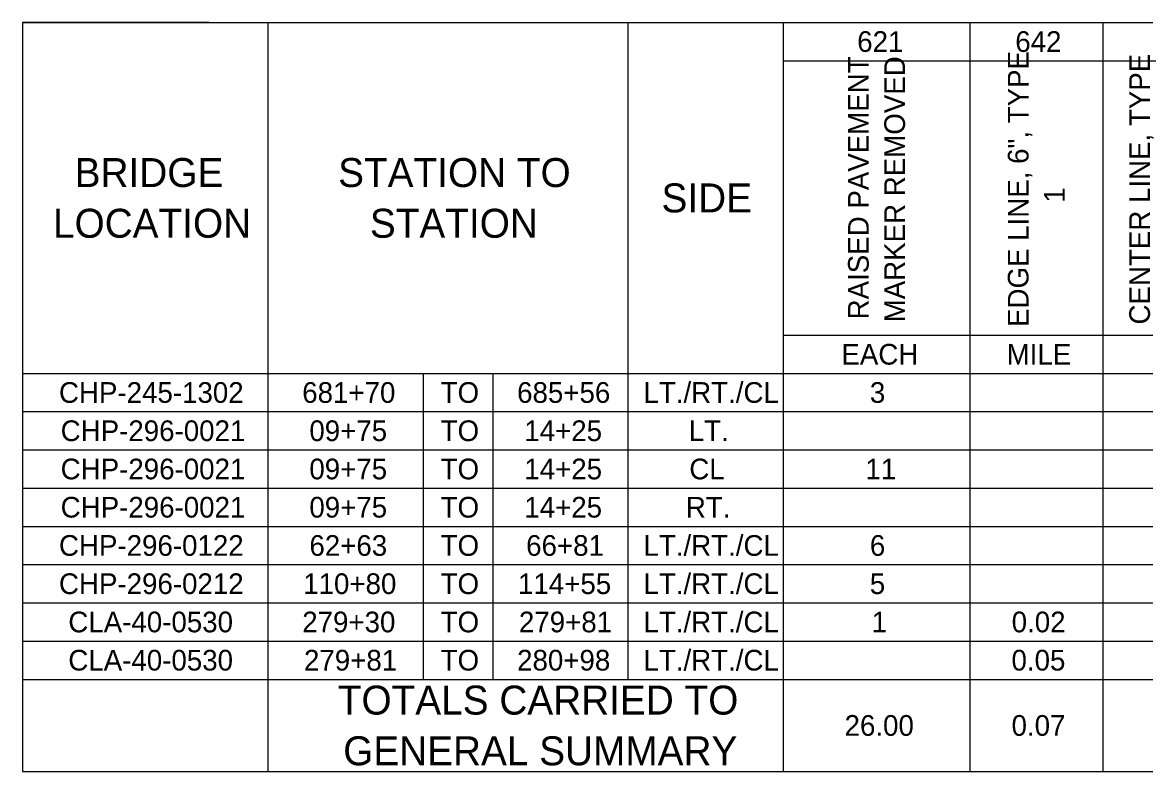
# Model space of a CAD drawing. Extents: x -49 to 78, y -12 to 34.
# Drawn here: x 9.03 to 17.24, y 28.25 to 33.74 of the extents above; entities that cross this region are included whole.
import ezdxf

# ---------------------------------------------------------------- set-up
doc = ezdxf.new("R2010")
doc.units = 0
doc.layers.add('SH_Text', color=7, linetype='Continuous')

msp = doc.modelspace()

# ---------------------------------------------------------------- linework, layer by layer
at = {"layer": 'SH_Text'}
for p, q in [((9.028, 33.7363), (23.7197, 33.7363)), ((9.028, 33.7363), (9.028, 28.2516)), ((10.8232, 33.7363), (10.8232, 28.2516)), ((13.4585, 33.7363), (13.4585, 28.9268)), ((14.595, 33.7363), (14.595, 28.2516)), ((15.9621, 33.7363), (15.9621, 28.2516)), ((16.9338, 33.7363), (16.9338, 28.2516)), ((14.595, 33.4563), (23.7197, 33.4563)), ((14.595, 31.4468), (23.7197, 31.4468)), ((9.028, 31.1668), (23.7197, 31.1668)), ((11.9597, 31.1668), (11.9597, 28.9268)), ((12.4703, 31.1668), (12.4703, 28.9268)), ((9.028, 30.8868), (23.7197, 30.8868)), ((9.028, 30.6068), (23.7197, 30.6068)), ((9.028, 30.3268), (23.7197, 30.3268)), ((9.028, 30.0468), (23.7197, 30.0468)), ((9.028, 29.7668), (23.7197, 29.7668)), ((9.028, 29.4868), (23.7197, 29.4868)), ((9.028, 29.2068), (23.7197, 29.2068)), ((9.028, 28.9268), (23.7197, 28.9268)), ((9.028, 28.2516), (23.7197, 28.2516))]:
    msp.add_line(p, q, dxfattribs=at)
for points in [[(9.028, 33.7363), (9.028, 33.7363), (9.028, 33.7363), (9.028, 33.7363)], [(9.028, 33.7363), (9.028, 33.7363), (9.028, 33.7363), (9.028, 33.7363)], [(9.028, 33.7363), (9.5385, 33.7363), (9.5385, 33.7363), (9.028, 33.7363)], [(9.028, 33.7363), (9.028, 33.7363), (9.028, 33.7363), (9.028, 33.7363)], [(9.028, 33.7363), (10.1644, 33.7363), (10.1644, 33.7363), (9.028, 33.7363)], [(9.028, 33.7363), (10.395, 33.7363), (10.395, 33.7363), (9.028, 33.7363)], [(9.028, 33.7363), (9.9997, 33.7363), (9.9997, 33.7363), (9.028, 33.7363)], [(9.028, 33.7363), (10.0985, 33.7363), (10.0985, 33.7363), (9.028, 33.7363)], [(9.028, 33.7363), (9.9668, 33.7363), (9.9668, 33.7363), (9.028, 33.7363)], [(9.028, 33.7363), (9.8185, 33.7363), (9.8185, 33.7363), (9.028, 33.7363)], [(9.028, 33.7363), (9.9174, 33.7363), (9.9174, 33.7363), (9.028, 33.7363)], [(9.028, 33.7363), (9.9338, 33.7363), (9.9338, 33.7363), (9.028, 33.7363)], [(9.028, 33.7363), (9.9174, 33.7363), (9.9174, 33.7363), (9.028, 33.7363)], [(9.028, 33.7363), (10.3291, 33.7363), (10.3291, 33.7363), (9.028, 33.7363)], [(9.028, 33.7363), (9.028, 33.7363), (9.028, 33.7363), (9.028, 33.7363)], [(9.028, 33.7363), (9.028, 33.7363), (9.028, 33.7363), (9.028, 33.7363)], [(9.028, 33.7363), (9.5385, 33.7363), (9.5385, 33.7363), (9.028, 33.7363)], [(9.028, 33.7363), (9.028, 33.7363), (9.028, 33.7363), (9.028, 33.7363)], [(9.028, 33.7363), (10.1644, 33.7363), (10.1644, 33.7363), (9.028, 33.7363)], [(9.028, 33.7363), (10.395, 33.7363), (10.395, 33.7363), (9.028, 33.7363)], [(9.028, 33.7363), (9.9997, 33.7363), (9.9997, 33.7363), (9.028, 33.7363)], [(9.028, 33.7363), (10.0985, 33.7363), (10.0985, 33.7363), (9.028, 33.7363)], [(9.028, 33.7363), (9.9668, 33.7363), (9.9668, 33.7363), (9.028, 33.7363)], [(9.028, 33.7363), (9.8185, 33.7363), (9.8185, 33.7363), (9.028, 33.7363)], [(9.028, 33.7363), (9.9174, 33.7363), (9.9174, 33.7363), (9.028, 33.7363)], [(9.028, 33.7363), (9.9338, 33.7363), (9.9338, 33.7363), (9.028, 33.7363)], [(9.028, 33.7363), (9.9174, 33.7363), (9.9174, 33.7363), (9.028, 33.7363)], [(9.028, 33.7363), (10.3291, 33.7363), (10.3291, 33.7363), (9.028, 33.7363)], [(9.028, 33.7363), (9.028, 33.7363), (9.028, 33.7363), (9.028, 33.7363)], [(9.028, 33.7363), (9.028, 33.7363), (9.028, 33.7363), (9.028, 33.7363)], [(9.028, 33.7363), (9.5385, 33.7363), (9.5385, 33.7363), (9.028, 33.7363)], [(9.028, 33.7363), (9.028, 33.7363), (9.028, 33.7363), (9.028, 33.7363)], [(9.028, 33.7363), (10.1644, 33.7363), (10.1644, 33.7363), (9.028, 33.7363)], [(9.028, 33.7363), (10.395, 33.7363), (10.395, 33.7363), (9.028, 33.7363)], [(9.028, 33.7363), (9.9997, 33.7363), (9.9997, 33.7363), (9.028, 33.7363)], [(9.028, 33.7363), (10.0985, 33.7363), (10.0985, 33.7363), (9.028, 33.7363)], [(9.028, 33.7363), (9.9668, 33.7363), (9.9668, 33.7363), (9.028, 33.7363)], [(9.028, 33.7363), (9.8185, 33.7363), (9.8185, 33.7363), (9.028, 33.7363)], [(9.028, 33.7363), (9.9174, 33.7363), (9.9174, 33.7363), (9.028, 33.7363)], [(9.028, 33.7363), (9.9338, 33.7363), (9.9338, 33.7363), (9.028, 33.7363)], [(9.028, 33.7363), (9.9174, 33.7363), (9.9174, 33.7363), (9.028, 33.7363)], [(9.028, 33.7363), (10.3291, 33.7363), (10.3291, 33.7363), (9.028, 33.7363)], [(9.028, 33.7363), (9.028, 33.7363), (9.028, 33.7363), (9.028, 33.7363)], [(9.028, 33.7363), (9.028, 33.7363), (9.028, 33.7363), (9.028, 33.7363)], [(9.028, 33.7363), (9.5385, 33.7363), (9.5385, 33.7363), (9.028, 33.7363)], [(9.028, 33.7363), (9.028, 33.7363), (9.028, 33.7363), (9.028, 33.7363)], [(9.028, 33.7363), (10.1644, 33.7363), (10.1644, 33.7363), (9.028, 33.7363)], [(9.028, 33.7363), (10.395, 33.7363), (10.395, 33.7363), (9.028, 33.7363)], [(9.028, 33.7363), (9.9997, 33.7363), (9.9997, 33.7363), (9.028, 33.7363)], [(9.028, 33.7363), (10.0985, 33.7363), (10.0985, 33.7363), (9.028, 33.7363)], [(9.028, 33.7363), (9.9668, 33.7363), (9.9668, 33.7363), (9.028, 33.7363)], [(9.028, 33.7363), (9.8185, 33.7363), (9.8185, 33.7363), (9.028, 33.7363)], [(9.028, 33.7363), (9.9174, 33.7363), (9.9174, 33.7363), (9.028, 33.7363)], [(9.028, 33.7363), (9.9338, 33.7363), (9.9338, 33.7363), (9.028, 33.7363)], [(9.028, 33.7363), (9.9174, 33.7363), (9.9174, 33.7363), (9.028, 33.7363)], [(9.028, 33.7363), (10.3291, 33.7363), (10.3291, 33.7363), (9.028, 33.7363)], [(9.028, 33.7363), (9.9997, 33.7363), (9.9997, 33.7363), (9.028, 33.7363)], [(9.028, 33.7363), (9.8515, 33.7363), (9.8515, 33.7363), (9.028, 33.7363)], [(9.028, 33.7363), (9.028, 33.7363), (9.028, 33.7363), (9.028, 33.7363)], [(9.028, 33.7363), (9.5385, 33.7363), (9.5385, 33.7363), (9.028, 33.7363)], [(9.028, 33.7363), (9.028, 33.7363), (9.028, 33.7363), (9.028, 33.7363)], [(9.028, 33.7363), (10.1644, 33.7363), (10.1644, 33.7363), (9.028, 33.7363)], [(9.028, 33.7363), (10.395, 33.7363), (10.395, 33.7363), (9.028, 33.7363)], [(9.028, 33.7363), (9.9997, 33.7363), (9.9997, 33.7363), (9.028, 33.7363)], [(9.028, 33.7363), (10.0985, 33.7363), (10.0985, 33.7363), (9.028, 33.7363)], [(9.028, 33.7363), (9.9668, 33.7363), (9.9668, 33.7363), (9.028, 33.7363)], [(9.028, 33.7363), (9.8185, 33.7363), (9.8185, 33.7363), (9.028, 33.7363)], [(9.028, 33.7363), (9.9174, 33.7363), (9.9174, 33.7363), (9.028, 33.7363)], [(9.028, 33.7363), (9.9338, 33.7363), (9.9338, 33.7363), (9.028, 33.7363)], [(9.028, 33.7363), (9.9174, 33.7363), (9.9174, 33.7363), (9.028, 33.7363)], [(9.028, 33.7363), (10.3291, 33.7363), (10.3291, 33.7363), (9.028, 33.7363)], [(9.028, 33.7363), (9.9997, 33.7363), (9.9997, 33.7363), (9.028, 33.7363)], [(9.028, 33.7363), (9.8515, 33.7363), (9.8515, 33.7363), (9.028, 33.7363)], [(9.028, 33.7363), (9.6868, 33.7363), (9.6868, 33.7363), (9.028, 33.7363)], [(9.028, 33.7363), (9.5056, 33.7363), (9.5056, 33.7363), (9.028, 33.7363)], [(9.028, 33.7363), (9.5385, 33.7363), (9.5385, 33.7363), (9.028, 33.7363)], [(9.028, 33.7363), (9.6374, 33.7363), (9.6374, 33.7363), (9.028, 33.7363)], [(9.028, 33.7363), (9.4068, 33.7363), (9.4068, 33.7363), (9.028, 33.7363)], [(9.028, 33.7363), (10.1644, 33.7363), (10.1644, 33.7363), (9.028, 33.7363)], [(9.028, 33.7363), (10.395, 33.7363), (10.395, 33.7363), (9.028, 33.7363)], [(9.028, 33.7363), (9.9997, 33.7363), (9.9997, 33.7363), (9.028, 33.7363)], [(9.028, 33.7363), (10.0985, 33.7363), (10.0985, 33.7363), (9.028, 33.7363)], [(9.028, 33.7363), (9.9668, 33.7363), (9.9668, 33.7363), (9.028, 33.7363)], [(9.028, 33.7363), (9.8185, 33.7363), (9.8185, 33.7363), (9.028, 33.7363)], [(9.028, 33.7363), (9.9174, 33.7363), (9.9174, 33.7363), (9.028, 33.7363)], [(9.028, 33.7363), (9.9338, 33.7363), (9.9338, 33.7363), (9.028, 33.7363)], [(9.028, 33.7363), (9.9174, 33.7363), (9.9174, 33.7363), (9.028, 33.7363)], [(9.028, 33.7363), (10.3291, 33.7363), (10.3291, 33.7363), (9.028, 33.7363)], [(9.028, 33.7363), (9.9997, 33.7363), (9.9997, 33.7363), (9.028, 33.7363)], [(9.028, 33.7363), (9.8515, 33.7363), (9.8515, 33.7363), (9.028, 33.7363)], [(9.028, 33.7363), (9.6868, 33.7363), (9.6868, 33.7363), (9.028, 33.7363)], [(9.028, 33.7363), (9.5056, 33.7363), (9.5056, 33.7363), (9.028, 33.7363)], [(9.028, 33.7363), (9.5385, 33.7363), (9.5385, 33.7363), (9.028, 33.7363)], [(9.028, 33.7363), (9.6374, 33.7363), (9.6374, 33.7363), (9.028, 33.7363)], [(9.028, 33.7363), (9.4068, 33.7363), (9.4068, 33.7363), (9.028, 33.7363)], [(9.028, 33.7363), (10.1644, 33.7363), (10.1644, 33.7363), (9.028, 33.7363)], [(9.028, 33.7363), (10.395, 33.7363), (10.395, 33.7363), (9.028, 33.7363)], [(9.028, 33.7363), (9.9997, 33.7363), (9.9997, 33.7363), (9.028, 33.7363)], [(9.028, 33.7363), (10.0985, 33.7363), (10.0985, 33.7363), (9.028, 33.7363)], [(9.028, 33.7363), (9.9668, 33.7363), (9.9668, 33.7363), (9.028, 33.7363)], [(9.028, 33.7363), (9.8185, 33.7363), (9.8185, 33.7363), (9.028, 33.7363)], [(9.028, 33.7363), (9.9174, 33.7363), (9.9174, 33.7363), (9.028, 33.7363)], [(9.028, 33.7363), (9.9338, 33.7363), (9.9338, 33.7363), (9.028, 33.7363)], [(9.028, 33.7363), (9.9174, 33.7363), (9.9174, 33.7363), (9.028, 33.7363)], [(9.028, 33.7363), (10.3291, 33.7363), (10.3291, 33.7363), (9.028, 33.7363)], [(9.028, 33.7363), (9.9997, 33.7363), (9.9997, 33.7363), (9.028, 33.7363)], [(9.028, 33.7363), (9.8515, 33.7363), (9.8515, 33.7363), (9.028, 33.7363)], [(9.028, 33.7363), (9.6868, 33.7363), (9.6868, 33.7363), (9.028, 33.7363)], [(9.028, 33.7363), (9.5056, 33.7363), (9.5056, 33.7363), (9.028, 33.7363)], [(9.028, 33.7363), (9.5385, 33.7363), (9.5385, 33.7363), (9.028, 33.7363)], [(9.028, 33.7363), (9.6374, 33.7363), (9.6374, 33.7363), (9.028, 33.7363)], [(9.028, 33.7363), (9.4068, 33.7363), (9.4068, 33.7363), (9.028, 33.7363)], [(9.028, 33.7363), (10.1644, 33.7363), (10.1644, 33.7363), (9.028, 33.7363)], [(9.028, 33.7363), (10.395, 33.7363), (10.395, 33.7363), (9.028, 33.7363)], [(9.028, 33.7363), (9.9997, 33.7363), (9.9997, 33.7363), (9.028, 33.7363)], [(9.028, 33.7363), (10.0985, 33.7363), (10.0985, 33.7363), (9.028, 33.7363)], [(9.028, 33.7363), (9.9668, 33.7363), (9.9668, 33.7363), (9.028, 33.7363)], [(9.028, 33.7363), (9.8185, 33.7363), (9.8185, 33.7363), (9.028, 33.7363)], [(9.028, 33.7363), (9.9174, 33.7363), (9.9174, 33.7363), (9.028, 33.7363)], [(9.028, 33.7363), (9.9338, 33.7363), (9.9338, 33.7363), (9.028, 33.7363)], [(9.028, 33.7363), (9.9174, 33.7363), (9.9174, 33.7363), (9.028, 33.7363)], [(9.028, 33.7363), (10.3291, 33.7363), (10.3291, 33.7363), (9.028, 33.7363)], [(9.028, 33.7363), (9.9997, 33.7363), (9.9997, 33.7363), (9.028, 33.7363)], [(9.028, 33.7363), (9.8515, 33.7363), (9.8515, 33.7363), (9.028, 33.7363)], [(9.028, 33.7363), (9.6868, 33.7363), (9.6868, 33.7363), (9.028, 33.7363)], [(9.028, 33.7363), (9.5056, 33.7363), (9.5056, 33.7363), (9.028, 33.7363)], [(9.028, 33.7363), (9.5385, 33.7363), (9.5385, 33.7363), (9.028, 33.7363)], [(9.028, 33.7363), (9.6374, 33.7363), (9.6374, 33.7363), (9.028, 33.7363)], [(9.028, 33.7363), (9.4068, 33.7363), (9.4068, 33.7363), (9.028, 33.7363)], [(9.028, 33.7363), (10.1644, 33.7363), (10.1644, 33.7363), (9.028, 33.7363)], [(9.028, 33.7363), (10.395, 33.7363), (10.395, 33.7363), (9.028, 33.7363)], [(9.028, 33.7363), (9.9997, 33.7363), (9.9997, 33.7363), (9.028, 33.7363)], [(9.028, 33.7363), (10.0985, 33.7363), (10.0985, 33.7363), (9.028, 33.7363)], [(9.028, 33.7363), (9.9668, 33.7363), (9.9668, 33.7363), (9.028, 33.7363)], [(9.028, 33.7363), (9.8185, 33.7363), (9.8185, 33.7363), (9.028, 33.7363)], [(9.028, 33.7363), (9.9174, 33.7363), (9.9174, 33.7363), (9.028, 33.7363)], [(9.028, 33.7363), (9.9338, 33.7363), (9.9338, 33.7363), (9.028, 33.7363)], [(9.028, 33.7363), (9.9174, 33.7363), (9.9174, 33.7363), (9.028, 33.7363)], [(9.028, 33.7363), (10.3291, 33.7363), (10.3291, 33.7363), (9.028, 33.7363)], [(9.028, 33.7363), (9.9997, 33.7363), (9.9997, 33.7363), (9.028, 33.7363)], [(9.028, 33.7363), (9.8515, 33.7363), (9.8515, 33.7363), (9.028, 33.7363)], [(9.028, 33.7363), (9.6868, 33.7363), (9.6868, 33.7363), (9.028, 33.7363)], [(9.028, 33.7363), (9.5056, 33.7363), (9.5056, 33.7363), (9.028, 33.7363)], [(9.028, 33.7363), (9.5385, 33.7363), (9.5385, 33.7363), (9.028, 33.7363)], [(9.028, 33.7363), (9.6374, 33.7363), (9.6374, 33.7363), (9.028, 33.7363)], [(9.028, 33.7363), (9.4068, 33.7363), (9.4068, 33.7363), (9.028, 33.7363)], [(9.028, 33.7363), (10.1644, 33.7363), (10.1644, 33.7363), (9.028, 33.7363)], [(9.028, 33.7363), (10.395, 33.7363), (10.395, 33.7363), (9.028, 33.7363)], [(9.028, 33.7363), (9.9997, 33.7363), (9.9997, 33.7363), (9.028, 33.7363)], [(9.028, 33.7363), (10.0985, 33.7363), (10.0985, 33.7363), (9.028, 33.7363)], [(9.028, 33.7363), (9.9668, 33.7363), (9.9668, 33.7363), (9.028, 33.7363)], [(9.028, 33.7363), (9.8185, 33.7363), (9.8185, 33.7363), (9.028, 33.7363)], [(9.028, 33.7363), (9.9174, 33.7363), (9.9174, 33.7363), (9.028, 33.7363)], [(9.028, 33.7363), (9.9338, 33.7363), (9.9338, 33.7363), (9.028, 33.7363)], [(9.028, 33.7363), (9.9174, 33.7363), (9.9174, 33.7363), (9.028, 33.7363)], [(9.028, 33.7363), (10.3291, 33.7363), (10.3291, 33.7363), (9.028, 33.7363)], [(9.028, 33.7363), (9.9997, 33.7363), (9.9997, 33.7363), (9.028, 33.7363)], [(9.028, 33.7363), (9.8515, 33.7363), (9.8515, 33.7363), (9.028, 33.7363)], [(9.028, 33.7363), (9.6868, 33.7363), (9.6868, 33.7363), (9.028, 33.7363)], [(9.028, 33.7363), (9.5056, 33.7363), (9.5056, 33.7363), (9.028, 33.7363)], [(9.028, 33.7363), (9.5385, 33.7363), (9.5385, 33.7363), (9.028, 33.7363)], [(9.028, 33.7363), (9.6374, 33.7363), (9.6374, 33.7363), (9.028, 33.7363)], [(9.028, 33.7363), (9.4068, 33.7363), (9.4068, 33.7363), (9.028, 33.7363)], [(9.028, 33.7363), (10.1644, 33.7363), (10.1644, 33.7363), (9.028, 33.7363)], [(9.028, 33.7363), (10.395, 33.7363), (10.395, 33.7363), (9.028, 33.7363)], [(9.028, 33.7363), (9.9997, 33.7363), (9.9997, 33.7363), (9.028, 33.7363)], [(9.028, 33.7363), (10.0985, 33.7363), (10.0985, 33.7363), (9.028, 33.7363)], [(9.028, 33.7363), (9.9668, 33.7363), (9.9668, 33.7363), (9.028, 33.7363)], [(9.028, 33.7363), (9.8185, 33.7363), (9.8185, 33.7363), (9.028, 33.7363)], [(9.028, 33.7363), (9.9174, 33.7363), (9.9174, 33.7363), (9.028, 33.7363)], [(9.028, 33.7363), (9.9338, 33.7363), (9.9338, 33.7363), (9.028, 33.7363)], [(9.028, 33.7363), (9.9174, 33.7363), (9.9174, 33.7363), (9.028, 33.7363)], [(9.028, 33.7363), (10.3291, 33.7363), (10.3291, 33.7363), (9.028, 33.7363)], [(9.028, 33.7363), (9.9997, 33.7363), (9.9997, 33.7363), (9.028, 33.7363)], [(9.028, 33.7363), (9.8515, 33.7363), (9.8515, 33.7363), (9.028, 33.7363)], [(9.028, 33.7363), (9.6868, 33.7363), (9.6868, 33.7363), (9.028, 33.7363)], [(9.028, 33.7363), (9.5056, 33.7363), (9.5056, 33.7363), (9.028, 33.7363)], [(9.028, 33.7363), (9.5385, 33.7363), (9.5385, 33.7363), (9.028, 33.7363)], [(9.028, 33.7363), (9.6374, 33.7363), (9.6374, 33.7363), (9.028, 33.7363)], [(9.028, 33.7363), (9.4068, 33.7363), (9.4068, 33.7363), (9.028, 33.7363)], [(9.028, 33.7363), (10.1644, 33.7363), (10.1644, 33.7363), (9.028, 33.7363)], [(9.028, 33.7363), (10.395, 33.7363), (10.395, 33.7363), (9.028, 33.7363)], [(9.028, 33.7363), (9.9997, 33.7363), (9.9997, 33.7363), (9.028, 33.7363)], [(9.028, 33.7363), (10.0985, 33.7363), (10.0985, 33.7363), (9.028, 33.7363)], [(9.028, 33.7363), (9.9668, 33.7363), (9.9668, 33.7363), (9.028, 33.7363)], [(9.028, 33.7363), (9.8185, 33.7363), (9.8185, 33.7363), (9.028, 33.7363)], [(9.028, 33.7363), (9.9174, 33.7363), (9.9174, 33.7363), (9.028, 33.7363)], [(9.028, 33.7363), (9.9338, 33.7363), (9.9338, 33.7363), (9.028, 33.7363)], [(9.028, 33.7363), (9.9174, 33.7363), (9.9174, 33.7363), (9.028, 33.7363)], [(9.028, 33.7363), (10.3291, 33.7363), (10.3291, 33.7363), (9.028, 33.7363)], [(9.028, 33.7363), (9.9997, 33.7363), (9.9997, 33.7363), (9.028, 33.7363)], [(9.028, 33.7363), (9.8515, 33.7363), (9.8515, 33.7363), (9.028, 33.7363)], [(9.028, 33.7363), (9.6868, 33.7363), (9.6868, 33.7363), (9.028, 33.7363)], [(9.028, 33.7363), (9.5056, 33.7363), (9.5056, 33.7363), (9.028, 33.7363)], [(9.028, 33.7363), (9.5385, 33.7363), (9.5385, 33.7363), (9.028, 33.7363)], [(9.028, 33.7363), (9.6374, 33.7363), (9.6374, 33.7363), (9.028, 33.7363)], [(9.028, 33.7363), (9.4068, 33.7363), (9.4068, 33.7363), (9.028, 33.7363)], [(9.028, 33.7363), (10.1644, 33.7363), (10.1644, 33.7363), (9.028, 33.7363)], [(9.028, 33.7363), (10.395, 33.7363), (10.395, 33.7363), (9.028, 33.7363)], [(9.028, 33.7363), (9.9997, 33.7363), (9.9997, 33.7363), (9.028, 33.7363)], [(9.028, 33.7363), (10.0985, 33.7363), (10.0985, 33.7363), (9.028, 33.7363)], [(9.028, 33.7363), (9.9668, 33.7363), (9.9668, 33.7363), (9.028, 33.7363)], [(9.028, 33.7363), (9.8185, 33.7363), (9.8185, 33.7363), (9.028, 33.7363)], [(9.028, 33.7363), (9.9174, 33.7363), (9.9174, 33.7363), (9.028, 33.7363)], [(9.028, 33.7363), (9.9338, 33.7363), (9.9338, 33.7363), (9.028, 33.7363)], [(9.028, 33.7363), (9.9174, 33.7363), (9.9174, 33.7363), (9.028, 33.7363)], [(9.028, 33.7363), (10.3291, 33.7363), (10.3291, 33.7363), (9.028, 33.7363)], [(9.028, 33.7363), (9.028, 33.7363), (9.028, 33.7363), (9.028, 33.7363)], [(9.028, 33.7363), (9.028, 33.7363), (9.028, 33.7363), (9.028, 33.7363)], [(9.028, 33.7363), (9.5385, 33.7363), (9.5385, 33.7363), (9.028, 33.7363)], [(9.028, 33.7363), (9.028, 33.7363), (9.028, 33.7363), (9.028, 33.7363)], [(9.028, 33.7363), (10.1644, 33.7363), (10.1644, 33.7363), (9.028, 33.7363)], [(9.028, 33.7363), (10.395, 33.7363), (10.395, 33.7363), (9.028, 33.7363)], [(9.028, 33.7363), (9.9997, 33.7363), (9.9997, 33.7363), (9.028, 33.7363)], [(9.028, 33.7363), (10.0985, 33.7363), (10.0985, 33.7363), (9.028, 33.7363)], [(9.028, 33.7363), (9.9668, 33.7363), (9.9668, 33.7363), (9.028, 33.7363)], [(9.028, 33.7363), (9.8185, 33.7363), (9.8185, 33.7363), (9.028, 33.7363)], [(9.028, 33.7363), (9.9174, 33.7363), (9.9174, 33.7363), (9.028, 33.7363)], [(9.028, 33.7363), (9.9338, 33.7363), (9.9338, 33.7363), (9.028, 33.7363)], [(9.028, 33.7363), (9.9174, 33.7363), (9.9174, 33.7363), (9.028, 33.7363)], [(9.028, 33.7363), (10.3291, 33.7363), (10.3291, 33.7363), (9.028, 33.7363)]]:
    msp.add_lwpolyline(points, close=True, dxfattribs=at)

# ---------------------------------------------------------------- texts
for s, height, p in [('621', 0.15153, (15.1372, 33.5205)), ('642', 0.15153, (16.2941, 33.5205)), ('BRIDGE ', 0.21214, (9.4103, 32.5311)), ('STATION TO', 0.21214, (11.3384, 32.5311)), ('SIDE', 0.21214, (13.7049, 32.3455)), ('LOCATION', 0.21214, (9.2515, 32.1599)), ('STATION', 0.21214, (11.5708, 32.1599)), ('EACH', 0.15153, (15.0215, 31.2311)), ('MILE', 0.15153, (16.2307, 31.2311)), ('CHP-245-1302', 0.15153, (9.2953, 30.9511)), ('681+70', 0.15153, (11.0756, 30.9511)), ('TO', 0.15153, (12.0887, 30.9511)), ('685+56', 0.15153, (12.6483, 30.9511)), ('LT./RT./CL', 0.15153, (13.5732, 30.9511)), ('3', 0.1515, (15.2299, 30.9511)), ('CHP-296-0021', 0.15153, (9.3078, 30.6711)), ('09+75', 0.15153, (11.1278, 30.6711)), ('TO', 0.15153, (12.0887, 30.6711)), ('14+25', 0.15153, (12.7008, 30.6711)), ('LT.', 0.15153, (13.9045, 30.6711)), ('CHP-296-0021', 0.15153, (9.3078, 30.3911)), ('09+75', 0.15153, (11.1278, 30.3911)), ('TO', 0.15153, (12.0887, 30.3911)), ('14+25', 0.15153, (12.7008, 30.3911)), ('CL', 0.15153, (13.9084, 30.3911)), ('11', 0.15153, (15.1972, 30.3911)), ('CHP-296-0021', 0.15153, (9.3078, 30.1111)), ('09+75', 0.15153, (11.1278, 30.1111)), ('TO', 0.15153, (12.0887, 30.1111)), ('14+25', 0.15153, (12.7008, 30.1111)), ('RT.', 0.15153, (13.8833, 30.1111)), ('CHP-296-0122', 0.15153, (9.2953, 29.8311)), ('62+63', 0.15153, (11.1283, 29.8311)), ('TO', 0.15153, (12.0887, 29.8311)), ('66+81', 0.15153, (12.7145, 29.8311)), ('LT./RT./CL', 0.15153, (13.5732, 29.8311)), ('6', 0.1515, (15.2299, 29.8311)), ('CHP-296-0212', 0.15153, (9.2953, 29.5511)), ('110+80', 0.15153, (11.0827, 29.5511)), ('TO', 0.15153, (12.0887, 29.5511)), ('114+55', 0.15153, (12.6549, 29.5511)), ('LT./RT./CL', 0.15153, (13.5732, 29.5511)), ('5', 0.1515, (15.2294, 29.5511)), ('CLA-40-0530', 0.15153, (9.3637, 29.2711)), ('279+30', 0.15153, (11.0756, 29.2711)), ('TO', 0.15153, (12.0887, 29.2711)), ('279+81', 0.15153, (12.6615, 29.2711)), ('LT./RT./CL', 0.15153, (13.5732, 29.2711)), ('1', 0.1515, (15.2431, 29.2711)), ('0.02', 0.15153, (16.2677, 29.2711)), ('CLA-40-0530', 0.15153, (9.3637, 28.9911)), ('279+81', 0.15153, (11.0886, 28.9911)), ('TO', 0.15153, (12.0887, 28.9911)), ('280+98', 0.15153, (12.6482, 28.9911)), ('LT./RT./CL', 0.15153, (13.5732, 28.9911)), ('0.05', 0.15153, (16.2664, 28.9911)), ('TOTALS CARRIED TO', 0.212141, (11.3359, 28.6688)), ('26.00', 0.15153, (15.0448, 28.5134)), ('0.07', 0.15153, (16.2669, 28.5134)), ('GENERAL SUMMARY', 0.212141, (11.3753, 28.2975))]:
    msp.add_text(s, height=height, dxfattribs=at).set_placement(p)
for s, height, p in [('EDGE LINE, 6", TYPE ', 0.15153, (16.3911, 31.5068)), ('RAISED PAVEMENT ', 0.15153, (15.2217, 31.5622)), ('MARKER REMOVED', 0.15153, (15.4869, 31.5407)), ('CENTER LINE, TYPE ', 0.15153, (17.2797, 31.5248)), ('1', 0.1515, (16.6563, 32.4161))]:
    msp.add_text(s, height=height, rotation=90, dxfattribs=at).set_placement(p)

doc.saveas('drawing.dxf')
